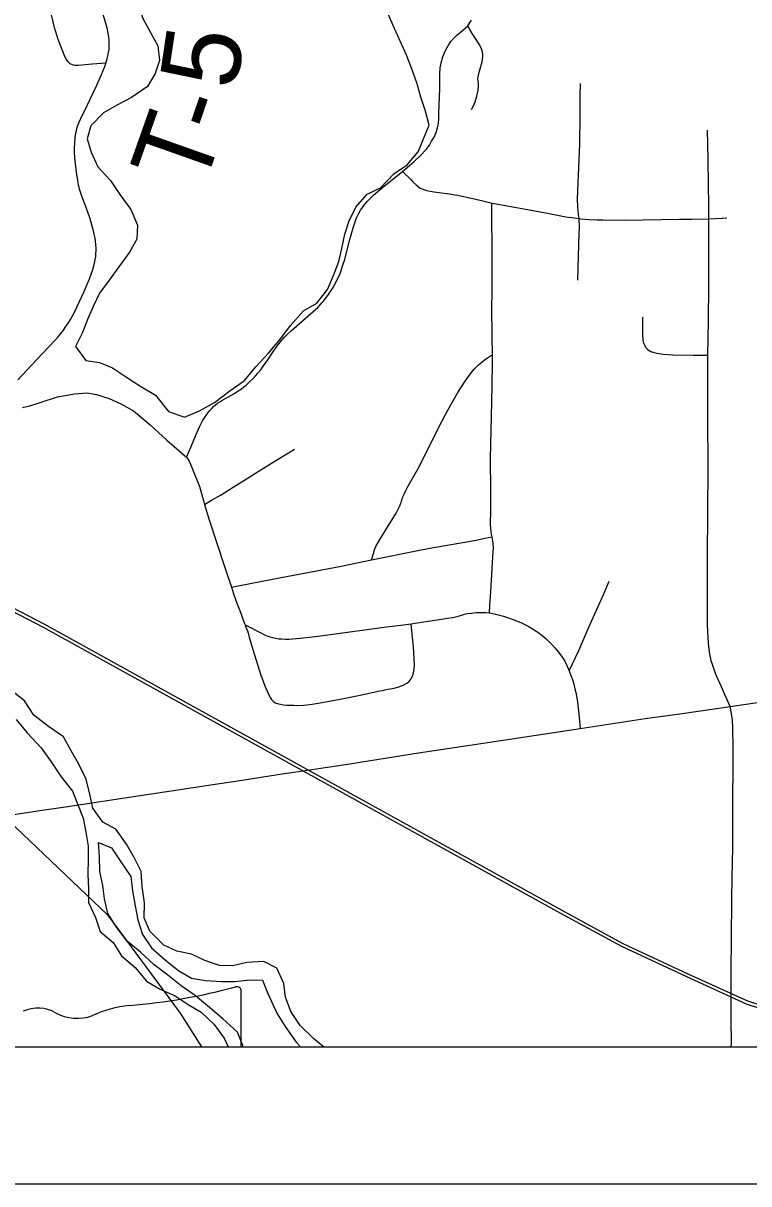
# Model space of a CAD drawing. Extents: x 0 to 34, y 0 to 22.
# Drawn here: x 4.032 to 4.562, y 13.717 to 14.566 of the extents above; entities that cross this region are included whole.
import ezdxf

# ---------------------------------------------------------------- set-up
doc = ezdxf.new("R2010")
doc.units = 0
for name, color, linetype in [('Default', 7, 'Continuous'), ('GM_X_Corporation', 7, 'Continuous'), ('GM_X_Major_Lake', 7, 'Continuous'), ('GM_X_Minor_River', 7, 'Continuous'), ('GM_X_Rail_Line', 7, 'Continuous'), ('GM_X_State_Route', 7, 'Continuous'), ('GM_X_Township_Road', 7, 'Continuous'), ('GM_X_Township_Road_Text', 7, 'Continuous'), ('SH_Data', 7, 'Continuous')]:
    doc.layers.add(name, color=color, linetype=linetype)

msp = doc.modelspace()

# ---------------------------------------------------------------- linework, layer by layer
at = {"layer": 'Default'}
msp.add_lwpolyline([(3.86154, 13.84949), (3.86154, 13.81727), (4.19112, 13.81727), (4.19112, 13.8581)], dxfattribs=at)
for centre, major_axis, start_param, end_param in [((4.07372, 14.12579), (0.34952, 0), 4.814394, 5.042369), ((4.18747, 13.85836), (0.00367, 0), 6.197627, 7.989034), ((4.04244, 13.82785), (0.02221, 0), 0.950623, 2.079405), ((4.1183, 13.79184), (0.07032, 0), 1.699012, 2.107814), ((4.07111, 13.85958), (0.02672, 0), 4.08156, 5.145723)]:
    msp.add_ellipse(centre, major_axis=major_axis, ratio=0.8, start_param=start_param, end_param=end_param, dxfattribs=at)
at = {"layer": 'GM_X_Corporation'}
msp.add_lwpolyline([(4.73203, 17.21351), (3.72594, 17.21067), (3.5941, 17.2097), (3.48484, 17.20877), (3.05968, 17.20671), (2.64928, 17.21019), (2.59523, 17.20975), (2.15896, 17.20547), (2.11404, 17.20482), (2.11404, 13.81727), (5.05386, 13.81727)], dxfattribs=at)
at = {"layer": 'GM_X_Major_Lake'}
for points in [[(4.07442, 14.66422), (4.08434, 14.65444), (4.08897, 14.64309), (4.09473, 14.63176), (4.09974, 14.6208), (4.10398, 14.61022), (4.10634, 14.59886), (4.11248, 14.58866), (4.11596, 14.57883), (4.11906, 14.569), (4.12482, 14.5588), (4.1302, 14.54898), (4.13141, 14.53837), (4.12808, 14.52886), (4.12248, 14.51934), (4.11081, 14.51128), (4.10063, 14.50589), (4.09045, 14.50012), (4.08107, 14.49057), (4.07849, 14.48107), (4.08122, 14.47123), (4.08622, 14.46065), (4.09538, 14.45048), (4.10227, 14.44029)], [(4.10227, 14.44029), (4.11031, 14.42936), (4.11531, 14.41802), (4.11464, 14.40777), (4.10941, 14.39825), (4.10155, 14.38757), (4.09443, 14.37765), (4.08731, 14.36811), (4.08285, 14.3586), (4.07876, 14.34908), (4.07505, 14.33957), (4.06983, 14.32929), (4.07747, 14.31911), (4.08733, 14.31767), (4.09682, 14.31357), (4.10709, 14.30683), (4.11698, 14.30046), (4.12839, 14.29372), (4.13794, 14.28166), (4.14971, 14.27758), (4.16065, 14.28222), (4.17158, 14.28837), (4.18287, 14.2968), (4.1934, 14.30447), (4.20165, 14.3144), (4.21104, 14.32433), (4.22004, 14.33502), (4.22716, 14.34456), (4.23654, 14.35525), (4.24633, 14.36102), (4.25421, 14.37094), (4.25867, 14.38122), (4.26237, 14.39148), (4.26457, 14.40098), (4.26676, 14.41124), (4.27009, 14.42113), (4.27494, 14.43103), (4.28319, 14.44057), (4.29299, 14.4452), (4.30275, 14.45552), (4.31255, 14.46204), (4.32042, 14.47159), (4.32451, 14.4811), (4.32859, 14.49099), (4.32587, 14.50121), (4.32238, 14.51143), (4.31965, 14.52126), (4.31578, 14.53223), (4.31192, 14.54206), (4.30769, 14.55189), (4.30307, 14.56171), (4.29883, 14.57154)]]:
    msp.add_lwpolyline(points, dxfattribs=at)
at = {"layer": 'GM_X_Minor_River'}
for points in [[(4.18498, 13.87658), (4.17514, 13.87689), (4.16451, 13.88059), (4.15464, 13.88507), (4.14402, 13.88726), (4.13452, 13.89174), (4.12422, 13.9019), (4.11999, 13.91172), (4.12028, 13.92272), (4.11867, 13.93447), (4.11783, 13.94546), (4.11283, 13.95566), (4.10708, 13.96548), (4.09943, 13.97642), (4.08992, 13.98165), (4.08265, 13.99184), (4.0803, 14.00206), (4.07757, 14.01304), (4.07219, 14.02399), (4.06681, 14.03381), (4.06106, 14.04401), (4.05002, 14.05151), (4.03936, 14.05977), (4.03247, 14.07033), (4.02104, 14.07935)], [(4.02651, 14.05663), (4.03454, 14.04683), (4.04484, 14.03592), (4.05211, 14.02573), (4.05939, 14.01479), (4.0678, 14.00424), (4.07552, 13.98457), (4.07749, 13.97435), (4.07908, 13.96412), (4.07916, 13.95426), (4.07886, 13.94364), (4.07933, 13.93264), (4.0794, 13.92278), (4.08441, 13.91182), (4.08789, 13.90161), (4.09742, 13.89372), (4.10355, 13.88391), (4.11346, 13.87526), (4.12186, 13.86547), (4.13174, 13.85947), (4.14276, 13.85463), (4.15227, 13.84826), (4.16178, 13.84265), (4.17131, 13.83362), (4.17857, 13.82381), (4.18146, 13.81727)], [(4.0899, 13.93538), (4.08755, 13.9456), (4.08747, 13.9566), (4.08663, 13.96684), (4.09613, 13.96274), (4.10302, 13.95255), (4.11029, 13.94199), (4.11151, 13.93138), (4.11348, 13.9204), (4.11546, 13.91017), (4.11894, 13.89958), (4.12545, 13.88977), (4.13574, 13.88075), (4.14526, 13.87324), (4.15477, 13.86762), (4.165, 13.86581), (4.17674, 13.86514), (4.18658, 13.86522), (4.19679, 13.86644), (4.20663, 13.86613), (4.2105, 13.8563), (4.21704, 13.84194), (4.22317, 13.83213), (4.23121, 13.82081), (4.23442, 13.81727)], [(4.19236, 13.81727), (4.19224, 13.81823), (4.18838, 13.82806), (4.17771, 13.83784), (4.1678, 13.84611), (4.15752, 13.85475), (4.14724, 13.86187), (4.13734, 13.86976), (4.12744, 13.87727), (4.11753, 13.88667), (4.10763, 13.89456), (4.09998, 13.90474), (4.09347, 13.91493), (4.09112, 13.92553), (4.0899, 13.93538)], [(4.25124, 13.81727), (4.24406, 13.82357), (4.23414, 13.83297), (4.22725, 13.84316), (4.22338, 13.85375), (4.22217, 13.8636), (4.21716, 13.87494), (4.20766, 13.8798), (4.19518, 13.87894), (4.18498, 13.87658)]]:
    msp.add_lwpolyline(points, dxfattribs=at)
at = {"layer": 'GM_X_Rail_Line'}
for points in [[(4.60878, 13.83531), (4.56159, 13.85082), (4.51794, 13.87054), (4.4705, 13.89269), (4.42806, 13.91569), (4.04753, 14.12601), (3.57732, 14.37047), (3.17701, 14.58711), (3.04274, 14.65987)], [(4.60803, 13.8331), (4.56074, 13.84864), (4.51696, 13.86842), (4.46944, 13.8906), (4.42693, 13.91364), (4.04642, 14.12395), (3.57622, 14.36841), (3.17589, 14.58506), (3.04162, 14.65782)], [(3.08634, 14.54716), (3.10413, 14.52486), (3.11991, 14.50949), (3.1737, 14.48963), (3.23031, 14.47529), (3.25659, 14.47436), (3.28422, 14.46858), (3.30694, 14.45661), (3.35097, 14.42715), (3.44687, 14.39723), (3.54767, 14.37281), (3.59796, 14.34744), (3.66323, 14.29634), (3.74771, 14.22568), (3.82598, 14.15716), (3.88165, 14.11514), (4.09326, 13.91373), (4.14646, 13.84199), (4.16207, 13.81727)]]:
    msp.add_lwpolyline(points, dxfattribs=at)
at = {"layer": 'GM_X_State_Route'}
msp.add_line((4.22105, 14.01679), (4.2279, 14.01783), dxfattribs=at)
for points in [[(4.36811, 14.03943), (4.41157, 14.04602), (4.43906, 14.05015), (4.48646, 14.05727), (4.5135, 14.06107), (4.54862, 14.06611), (4.60521, 14.07443)], [(4.2279, 14.01783), (4.26735, 14.02373), (4.32069, 14.03224), (4.36811, 14.03943)], [(4.18175, 14.01082), (4.19173, 14.01231), (4.22105, 14.01679)], [(4.06261, 13.99288), (4.1139, 14.00068), (4.18175, 14.01082)], [(3.93851, 13.97399), (4.04387, 13.99003), (4.06261, 13.99288)]]:
    msp.add_lwpolyline(points, dxfattribs=at)
at = {"layer": 'GM_X_Township_Road'}
for points in [[(4.05683, 14.55465), (4.05485, 14.56134), (4.05116, 14.57674)], [(4.07619, 14.5008), (4.08538, 14.52028), (4.089, 14.52813), (4.09012, 14.53099), (4.09124, 14.53383), (4.09198, 14.53645), (4.09302, 14.5396), (4.09382, 14.54298), (4.09442, 14.54626), (4.09458, 14.54931), (4.09458, 14.55294), (4.0941, 14.55715), (4.09304, 14.56192), (4.089, 14.57621)], [(4.15115, 14.24837), (4.15443, 14.25611), (4.15791, 14.26436), (4.1605, 14.27054), (4.16284, 14.27491), (4.16429, 14.27714), (4.1659, 14.27961), (4.16702, 14.28103), (4.16822, 14.28255), (4.16947, 14.28385), (4.17087, 14.28528), (4.17237, 14.28653), (4.17381, 14.28773), (4.17543, 14.28881), (4.17698, 14.28984), (4.18567, 14.29468), (4.1889, 14.29676), (4.19134, 14.29834), (4.19278, 14.2995), (4.19466, 14.30101), (4.19699, 14.30323), (4.19954, 14.30568), (4.20151, 14.30781), (4.20329, 14.30973), (4.20533, 14.31231), (4.20747, 14.315), (4.20863, 14.31675), (4.21047, 14.3195), (4.21526, 14.32668), (4.21732, 14.32941), (4.2194, 14.33218), (4.22102, 14.33407), (4.22266, 14.33598), (4.22503, 14.3383), (4.22757, 14.3408), (4.23795, 14.34972), (4.24538, 14.35623), (4.247, 14.35786), (4.24879, 14.35965), (4.25003, 14.36105), (4.25119, 14.36236), (4.25262, 14.36422), (4.25441, 14.36654), (4.2558, 14.36862), (4.25779, 14.37163), (4.25929, 14.37431), (4.26078, 14.37697), (4.26209, 14.37979), (4.2631, 14.38197), (4.26414, 14.38473), (4.26502, 14.38711), (4.26597, 14.39014), (4.26684, 14.39293), (4.27019, 14.40667), (4.27331, 14.41671), (4.27549, 14.42321), (4.27677, 14.42614), (4.27835, 14.42889), (4.27977, 14.43088), (4.28092, 14.43249), (4.2834, 14.43538), (4.28791, 14.43975), (4.29594, 14.4467), (4.30892, 14.45714), (4.31748, 14.46447), (4.322, 14.46864), (4.32656, 14.47359), (4.32869, 14.47652), (4.33034, 14.47934), (4.33209, 14.48233), (4.3336, 14.48562), (4.33474, 14.48904), (4.33546, 14.49258), (4.33567, 14.49556), (4.33562, 14.50009), (4.33575, 14.50556), (4.33633, 14.51792), (4.33638, 14.52099), (4.33627, 14.52847), (4.33661, 14.53289), (4.33731, 14.53664), (4.33862, 14.54089), (4.33982, 14.54379), (4.34081, 14.54616), (4.34258, 14.54953), (4.34439, 14.55219), (4.3465, 14.55461), (4.34886, 14.55679), (4.35126, 14.55884), (4.35673, 14.56363), (4.35951, 14.56766)], [(4.35948, 14.50249), (4.36063, 14.50454), (4.36215, 14.50807), (4.36341, 14.51211), (4.36439, 14.51653), (4.36468, 14.51932), (4.36461, 14.52168), (4.36429, 14.52328), (4.36424, 14.52504), (4.36482, 14.52875), (4.36724, 14.53737), (4.36784, 14.54103), (4.36782, 14.54286), (4.36738, 14.54528), (4.36656, 14.5476), (4.3651, 14.55033), (4.36235, 14.55435), (4.35999, 14.55797), (4.35816, 14.56095), (4.35673, 14.56363)], [(4.09198, 14.53645), (4.08207, 14.53553), (4.07188, 14.53464), (4.06943, 14.53474), (4.06765, 14.53513), (4.06605, 14.53583), (4.06446, 14.53722), (4.06317, 14.53902), (4.06198, 14.54121), (4.05711, 14.5537), (4.05683, 14.55465)], [(4.4373, 14.37767), (4.43836, 14.41225), (4.43855, 14.41559), (4.43843, 14.41852), (4.43828, 14.42065), (4.43813, 14.42275), (4.43786, 14.42561), (4.43755, 14.42873), (4.43735, 14.43111), (4.43721, 14.43293), (4.43704, 14.43531), (4.43711, 14.43721), (4.43787, 14.45455), (4.43883, 14.47745), (4.43903, 14.49731), (4.43903, 14.51206), (4.43914, 14.5214)], [(4.02778, 14.30489), (4.04167, 14.31984), (4.05485, 14.3337), (4.05688, 14.33611), (4.0592, 14.33885), (4.06099, 14.34125), (4.06285, 14.34376), (4.06415, 14.34581), (4.06612, 14.34893), (4.06737, 14.35123), (4.06904, 14.35433), (4.07593, 14.36889), (4.08001, 14.37859), (4.08253, 14.38555), (4.08384, 14.39026), (4.08432, 14.39283), (4.08472, 14.39505), (4.08486, 14.39702), (4.08502, 14.39927), (4.08494, 14.40127), (4.08484, 14.40351), (4.08448, 14.40621), (4.0842, 14.40833), (4.08356, 14.4113), (4.08304, 14.41371), (4.08028, 14.42323), (4.07764, 14.43083), (4.0745, 14.43907), (4.07308, 14.44358), (4.07218, 14.4472), (4.07149, 14.45103), (4.07082, 14.45477), (4.06928, 14.46709), (4.06907, 14.47143), (4.06921, 14.47433), (4.06938, 14.47783), (4.06957, 14.48173), (4.07019, 14.48541), (4.07086, 14.48802), (4.07144, 14.49027), (4.0724, 14.49284), (4.0736, 14.49537), (4.0751, 14.49851), (4.07619, 14.5008)], [(4.54862, 14.06611), (4.54573, 14.07271), (4.54107, 14.08321), (4.53856, 14.08896), (4.53693, 14.0932), (4.53566, 14.09678), (4.53487, 14.09947), (4.53423, 14.10208), (4.53353, 14.1058), (4.53293, 14.11247), (4.53212, 14.12528), (4.53205, 14.13395), (4.53218, 14.14451), (4.53214, 14.17492), (4.53226, 14.20841), (4.53267, 14.24063), (4.53241, 14.27724), (4.53234, 14.31886), (4.53242, 14.32296), (4.53291, 14.34793), (4.53301, 14.37349), (4.53319, 14.39873), (4.53311, 14.42267), (4.5331, 14.4337), (4.53282, 14.44683), (4.53257, 14.46652), (4.53219, 14.48741)], [(4.30892, 14.45714), (4.31512, 14.45127), (4.31691, 14.44939), (4.31898, 14.44738), (4.32041, 14.4462), (4.32207, 14.44504), (4.32384, 14.44425), (4.32691, 14.44332), (4.33188, 14.4424), (4.34333, 14.44073), (4.34741, 14.44016), (4.34955, 14.43984), (4.35157, 14.43934), (4.35394, 14.43882), (4.36353, 14.43663), (4.36772, 14.43562), (4.37366, 14.43422), (4.37431, 14.43411), (4.37912, 14.43321), (4.4151, 14.42667), (4.42845, 14.4241), (4.43456, 14.4232), (4.43813, 14.42275), (4.43949, 14.42258), (4.44542, 14.42208), (4.4513, 14.42176), (4.45564, 14.42176), (4.47145, 14.4217), (4.51172, 14.42231), (4.52092, 14.42238), (4.53311, 14.42267), (4.54281, 14.42301), (4.54621, 14.4233)], [(4.37264, 14.13447), (4.37302, 14.14024), (4.37366, 14.14999), (4.37414, 14.15855), (4.37483, 14.17135), (4.3752, 14.17518), (4.37544, 14.17882), (4.37557, 14.18223), (4.37541, 14.18517), (4.37507, 14.18729), (4.3748, 14.18863), (4.3745, 14.19012), (4.37417, 14.19216), (4.37386, 14.19406), (4.37359, 14.19653), (4.37351, 14.19892), (4.37341, 14.20196), (4.37367, 14.2067), (4.37358, 14.2239), (4.37345, 14.24721), (4.37373, 14.2579), (4.3744, 14.28831), (4.37483, 14.31607), (4.37476, 14.32348), (4.37462, 14.33703), (4.37446, 14.35738), (4.3745, 14.36912), (4.37469, 14.39706), (4.37437, 14.42799), (4.37431, 14.43411)], [(4.48811, 14.32721), (4.48709, 14.3286), (4.48619, 14.33028), (4.48563, 14.33165), (4.48516, 14.33406), (4.48486, 14.33838), (4.48469, 14.35063)], [(4.48811, 14.32721), (4.48938, 14.32631), (4.49058, 14.32571), (4.49212, 14.32522), (4.49512, 14.32443), (4.49999, 14.32368), (4.50679, 14.32317), (4.52166, 14.32301), (4.52754, 14.32298), (4.53242, 14.32296)], [(4.28637, 14.17335), (4.28796, 14.17864), (4.28826, 14.17964), (4.2888, 14.18126), (4.28964, 14.1831), (4.29213, 14.18779), (4.29878, 14.19841), (4.30429, 14.20749), (4.30631, 14.21133), (4.30699, 14.21281), (4.30768, 14.2143), (4.30801, 14.21516), (4.30833, 14.21602), (4.30864, 14.2171), (4.30887, 14.21793), (4.30917, 14.21898), (4.30961, 14.21997), (4.31023, 14.22142), (4.31095, 14.22296), (4.31249, 14.22604), (4.31463, 14.2299), (4.32117, 14.24128), (4.33612, 14.27117), (4.34217, 14.28277), (4.34957, 14.29562), (4.35487, 14.30398), (4.35844, 14.30897), (4.36022, 14.3112), (4.36176, 14.31304), (4.36331, 14.31464), (4.36498, 14.31618), (4.36675, 14.31766), (4.36871, 14.31918), (4.37108, 14.32087), (4.37476, 14.32348)], [(4.03109, 14.28458), (4.0364, 14.28589), (4.044, 14.28834), (4.05663, 14.29248), (4.06917, 14.29455), (4.0783, 14.29546), (4.0853, 14.29409), (4.09458, 14.2912), (4.10295, 14.28739), (4.11238, 14.28221), (4.1244, 14.27201), (4.13672, 14.26089), (4.15115, 14.24837), (4.15178, 14.24732), (4.15292, 14.24543), (4.15395, 14.24322), (4.15505, 14.24085), (4.16045, 14.22697), (4.16363, 14.21575), (4.16421, 14.21384), (4.16744, 14.20332), (4.17879, 14.16856), (4.18392, 14.15327), (4.1855, 14.14857), (4.1882, 14.14098), (4.18999, 14.13635), (4.19333, 14.12721), (4.1939, 14.12573), (4.19452, 14.12414), (4.19555, 14.12146), (4.19608, 14.11984), (4.19675, 14.11778), (4.19966, 14.10775), (4.20531, 14.08898), (4.20873, 14.07989), (4.21215, 14.07273)], [(4.16421, 14.21384), (4.16933, 14.21681), (4.17629, 14.22085), (4.18523, 14.2264), (4.21311, 14.244), (4.23004, 14.25427)], [(4.18392, 14.15327), (4.18995, 14.15445), (4.22031, 14.16039), (4.26302, 14.16843), (4.28637, 14.17335), (4.32018, 14.18015), (4.33175, 14.18236), (4.35316, 14.1859), (4.3628, 14.18767), (4.36934, 14.18904), (4.3745, 14.19012)], [(4.43081, 14.09213), (4.43804, 14.10697), (4.44538, 14.12401), (4.45626, 14.14841), (4.4603, 14.15771)], [(4.1939, 14.12573), (4.20634, 14.11936), (4.20814, 14.11849), (4.21045, 14.11754), (4.21394, 14.1165), (4.21643, 14.116), (4.21858, 14.11567), (4.22065, 14.1155), (4.22339, 14.11541), (4.22579, 14.11541), (4.22857, 14.11555), (4.2315, 14.11577), (4.23418, 14.11597), (4.24735, 14.11764), (4.27423, 14.12118), (4.29729, 14.12442), (4.30785, 14.12565), (4.31535, 14.12657), (4.31981, 14.12721), (4.33762, 14.1299), (4.34192, 14.13062), (4.3456, 14.13127), (4.34897, 14.13201), (4.3522, 14.13293), (4.35436, 14.13351), (4.35633, 14.13398), (4.3595, 14.13441), (4.36301, 14.13474), (4.36554, 14.13482), (4.36788, 14.13485), (4.37007, 14.13474), (4.37264, 14.13447), (4.37507, 14.1341), (4.37693, 14.13372), (4.37991, 14.13299), (4.38285, 14.1321), (4.38577, 14.13116), (4.38929, 14.13001), (4.39553, 14.12745), (4.39802, 14.12622), (4.40104, 14.12473), (4.40422, 14.12282), (4.40682, 14.12128), (4.40873, 14.11997), (4.41127, 14.11805), (4.41395, 14.11582), (4.41684, 14.11292), (4.41877, 14.11084), (4.42065, 14.10869), (4.42298, 14.10604), (4.42596, 14.10198), (4.42795, 14.09866), (4.42944, 14.09559), (4.43081, 14.09213), (4.43217, 14.08871), (4.43325, 14.08589), (4.43432, 14.08241), (4.43515, 14.07909), (4.43581, 14.07644), (4.43639, 14.07362), (4.43676, 14.07118), (4.43798, 14.06075), (4.43906, 14.05015)], [(4.21215, 14.07273), (4.2132, 14.0712), (4.21438, 14.06995), (4.21593, 14.06892), (4.21833, 14.06814), (4.21987, 14.0678), (4.22175, 14.06746), (4.22432, 14.0672), (4.22698, 14.06703), (4.22967, 14.06699), (4.23238, 14.06694), (4.23658, 14.06711), (4.24145, 14.06763), (4.24881, 14.06873), (4.26342, 14.07158), (4.27806, 14.07438), (4.29253, 14.07749), (4.29443, 14.0779), (4.29622, 14.07829), (4.29842, 14.07869), (4.30293, 14.07953), (4.30712, 14.08068), (4.30998, 14.08185), (4.31211, 14.08311), (4.31356, 14.08427), (4.31518, 14.08613), (4.31637, 14.08828), (4.31716, 14.09061), (4.31761, 14.09305), (4.31779, 14.09678), (4.31708, 14.10977), (4.31588, 14.12141), (4.31535, 14.12657)], [(4.54953, 13.81727), (4.54954, 13.81994), (4.54937, 13.8373), (4.54935, 13.84102), (4.54934, 13.84723), (4.54941, 13.86399), (4.54972, 13.905), (4.54989, 13.91618), (4.54994, 13.92487), (4.55008, 13.94104), (4.55059, 13.96339), (4.55073, 13.98637), (4.55067, 13.99817), (4.55083, 14.02178), (4.55097, 14.03545), (4.5507, 14.05095), (4.55037, 14.05623), (4.54967, 14.06109), (4.54862, 14.06611)]]:
    msp.add_lwpolyline(points, dxfattribs=at)
at = {"layer": 'SH_Data'}
for p, q in [((2.11404, 13.81727), (8.91404, 13.81727)), ((2.01404, 13.71727), (9.01404, 13.71727))]:
    msp.add_line(p, q, dxfattribs=at)

# ---------------------------------------------------------------- texts
at = {"layer": 'GM_X_Township_Road_Text'}
for s, rotation, p in [('5', 81.55944, (4.18741, 14.51593)), ('-', 71.08094, (4.17717, 14.48286)), ('T', 70.51337, (4.16279, 14.44222))]:
    msp.add_text(s, height=0.05682, rotation=rotation, dxfattribs=at).set_placement(p)

doc.saveas('drawing.dxf')
